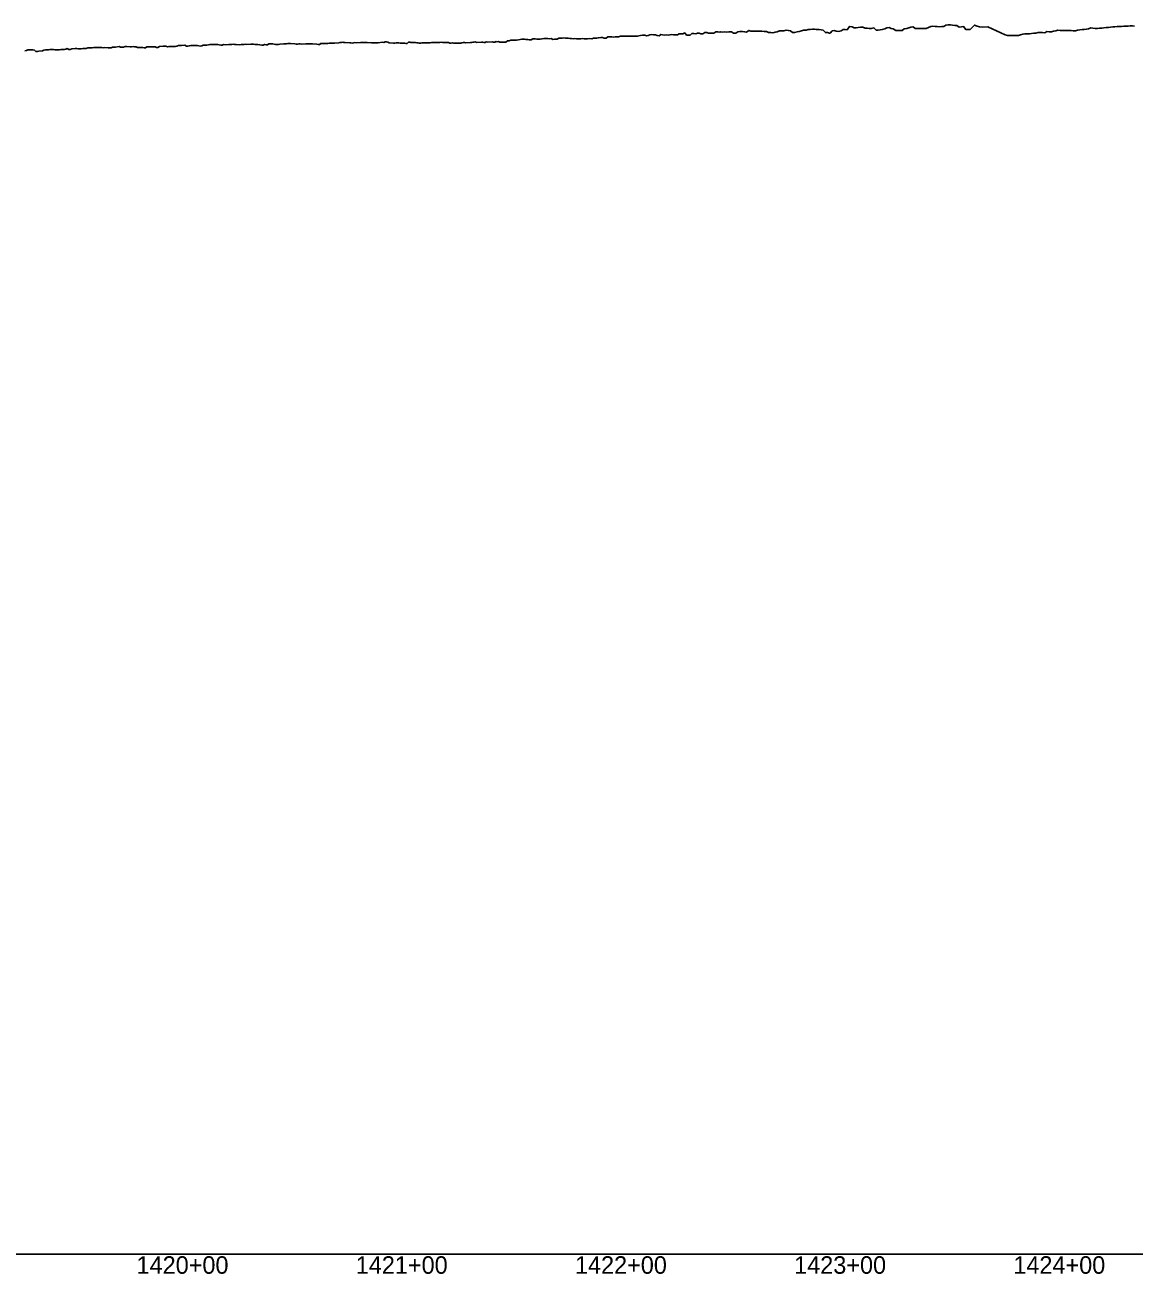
# Model space of a CAD drawing. Extents: x -3793 to 50787, y -1075 to 6138.
# Drawn here: x 29308 to 29813, y 991 to 1561 of the extents above; entities that cross this region are included whole.
import ezdxf

# ---------------------------------------------------------------- set-up
doc = ezdxf.new("R2010")
doc.units = 0
for name, color, linetype in [('RD_DDB_Profile_EX', 7, 'Continuous'), ('RD_DDB_StaTX', 7, 'Continuous'), ('RD_GPK_Profile_Cell', 7, 'Continuous')]:
    doc.layers.add(name, color=color, linetype=linetype)

msp = doc.modelspace()

# ---------------------------------------------------------------- linework, layer by layer
at = {"layer": 'RD_DDB_Profile_EX'}
for points in [[(29510.727296, 1552.70008), (29511.289844, 1552.672055), (29511.85211, 1552.89572), (29512.415515, 1552.95213), (29512.978802, 1553.00853), (29513.541972, 1552.811455), (29515.735563, 1552.906025), (29516.294395, 1552.90612), (29516.852944, 1552.736545), (29517.412638, 1552.73666), (29517.972213, 1553.044545), (29518.531671, 1552.820815), (29520.74402, 1553.006905), (29521.299048, 1552.896055), (29521.853791, 1552.83801), (29522.409686, 1553.143875), (29522.965461, 1553.1162), (29523.521117, 1553.1441), (29524.080917, 1552.9194), (29524.637441, 1552.863865), (29526.820946, 1552.860575), (29527.597675, 1553.52095), (29528.374319, 1553.521115), (29529.15088, 1553.793085), (29530.270517, 1553.864675), (29531.045117, 1553.861825), (29531.821316, 1553.86199), (29532.59743, 1553.97856), (29533.37346, 1554.05632), (29534.149406, 1554.211665), (29535.272139, 1554.27204), (29536.046109, 1554.036665), (29536.821687, 1554.11438), (29537.597179, 1553.959455), (29538.372587, 1553.959625), (29539.150156, 1554.422295), (29540.272077, 1554.4152), (29541.04711, 1554.29911), (29541.822059, 1554.260515), (29542.596922, 1554.22193), (29543.3717, 1554.3383), (29544.148651, 1554.49078), (29545.273723, 1554.494795), (29546.040367, 1554.572335), (29546.814688, 1554.456335), (29547.588923, 1554.49519), (29548.364538, 1554.10523), (29549.139398, 1554.22163), (29550.26763, 1554.305325), (29551.041392, 1554.653625), (29551.815068, 1554.769815), (29552.588659, 1554.769965), (29553.363636, 1554.8061), (29554.137855, 1554.69011), (29555.269317, 1554.69444), (29556.042427, 1554.578645), (29556.81545, 1554.50151), (29557.589064, 1554.45997), (29558.36272, 1554.498815), (29559.136289, 1554.344255), (29560.271021, 1554.45163), (29561.043471, 1554.37459), (29561.815834, 1554.52924), (29562.58879, 1554.448645), (29563.361788, 1554.448835), (29564.134699, 1554.449025), (29565.272744, 1554.48882), (29566.044525, 1554.45044), (29566.816219, 1554.68212), (29567.588509, 1554.678805), (29568.360841, 1554.678995), (29569.133086, 1554.872255), (29570.274485, 1554.957555), (29571.045589, 1554.996295), (29571.816474, 1554.68423), (29572.58822, 1554.68444), (29573.359879, 1555.26339), (29574.131449, 1555.263565), (29575.276244, 1555.303155), (29576.046662, 1555.22631), (29576.81686, 1555.261555), (29577.587925, 1555.30029), (29578.358901, 1555.33902), (29579.129788, 1555.57048), (29580.278023, 1555.621485), (29581.046786, 1555.57983), (29581.817248, 1555.58001), (29582.589017, 1555.573465), (29583.367111, 1555.56011), (29584.149479, 1555.627845), (29585.263496, 1555.632895), (29586.037114, 1555.584045), (29586.815605, 1555.570515), (29587.600158, 1555.835055), (29588.381972, 1555.9438), (29589.176798, 1556.01378), (29590.229218, 1556.14469), (29591.014, 1555.81378), (29591.80592, 1555.921455), (29592.603113, 1556.269125), (29593.407295, 1556.41578)], [(29593.407295, 1556.41578), (29594.21612, 1556.285525), (29595.199443, 1556.2209), (29595.998982, 1555.97004), (29596.803798, 1555.79464), (29597.615202, 1556.35215), (29598.432166, 1556.221055), (29599.249294, 1556.126605), (29600.159919, 1556.194445), (29600.973863, 1556.101645), (29601.793485, 1556.25508), (29602.618844, 1556.3683), (29603.4518, 1556.18855), (29604.289823, 1556.2192), (29605.128945, 1556.256815), (29605.95708, 1556.620805), (29606.790954, 1556.69085), (29607.632024, 1556.722835), (29608.47916, 1557.09289), (29609.326912, 1556.105155), (29610.085561, 1556.086265), (29610.929639, 1556.074315), (29611.779919, 1556.91623), (29612.637342, 1556.775465), (29613.501325, 1556.722855), (29614.371736, 1556.929225), (29615.050946, 1556.93858), (29615.909468, 1556.70917), (29616.776903, 1556.65544), (29617.650918, 1557.344705), (29618.531587, 1557.249085), (29619.413413, 1557.061545), (29620.003052, 1557.045935), (29620.880634, 1557.03741), (29621.765031, 1556.984395), (29622.657268, 1557.597735), (29623.556734, 1557.59126), (29624.463276, 1557.49472), (29624.964144, 1557.536325), (29625.857871, 1557.434625), (29626.761432, 1557.561945), (29627.672249, 1557.507985), (29628.592665, 1557.58805), (29629.510375, 1557.62567), (29629.910933, 1557.64706), (29630.82599, 1557.037655), (29631.74858, 1557.025875), (29632.67983, 1557.61592), (29633.619095, 1557.74685), (29634.566201, 1557.737865), (29634.866917, 1557.73588), (29635.800138, 1557.67666), (29636.744278, 1557.47764), (29637.696472, 1558.277565), (29638.659316, 1557.885145), (29639.817035, 1557.881045), (29640.764632, 1557.92032), (29641.729951, 1557.957005), (29642.705538, 1557.8994), (29643.689758, 1557.84129), (29644.753892, 1557.82962), (29645.735058, 1557.81984), (29646.725108, 1557.312235), (29647.724836, 1557.249965), (29648.716022, 1557.219115), (29649.741974, 1557.43547), (29650.728297, 1557.549385), (29651.718029, 1558.01174), (29652.699698, 1558.02468), (29653.78656, 1558.13589), (29654.774013, 1558.29865), (29655.751372, 1558.262075), (29656.722276, 1558.03236), (29657.685961, 1557.231135), (29658.643084, 1557.246435), (29659.81158, 1557.653895), (29660.762537, 1557.81153), (29661.717088, 1558.067605), (29662.664218, 1558.36462), (29663.887678, 1558.42827), (29664.840344, 1558.63242), (29665.783709, 1558.73752), (29666.72089, 1558.83831), (29667.656454, 1558.881245), (29668.592367, 1558.647095), (29669.531158, 1558.59618), (29669.845994, 1558.616765), (29670.783212, 1558.47594), (29671.720296, 1558.33055), (29672.65873, 1557.29807), (29673.599038, 1557.245125), (29674.538691, 1557.056915), (29674.840419, 1557.04589), (29675.779008, 1558.121865), (29676.719947, 1558.21571), (29677.661756, 1557.83415), (29678.603913, 1557.833885), (29679.83264, 1558.132795), (29680.774824, 1558.69421), (29681.719361, 1558.646745), (29682.664769, 1558.452915)], [(29682.664769, 1558.452915), (29683.610527, 1560.06029), (29684.824896, 1559.82218), (29685.771904, 1559.44317), (29686.718779, 1559.43931), (29687.667006, 1559.62875), (29688.617114, 1559.672555), (29689.819433, 1559.786535), (29690.767759, 1559.307305), (29691.718441, 1559.35461), (29692.669996, 1559.112275), (29693.623674, 1559.1076), (29694.81176, 1559.437465), (29695.763633, 1558.383615), (29696.717867, 1558.38334), (29697.672974, 1558.473455), (29698.628431, 1558.61649), (29699.80412, 1558.962325), (29700.760774, 1559.488255), (29701.717295, 1559.62731), (29702.675173, 1559.05238), (29703.634935, 1558.951385), (29704.798767, 1558.17858), (29705.756688, 1558.220655), (29706.716728, 1558.21476), (29707.678127, 1558.21446), (29708.641414, 1559.02661), (29709.791197, 1559.09404), (29710.752619, 1559.474015), (29711.716406, 1559.762895), (29712.68107, 1559.95108), (29713.646084, 1559.17891), (29714.78366, 1559.075895), (29715.74982, 1559.123925), (29716.715846, 1559.11845), (29717.683232, 1559.0698), (29718.652508, 1559.06426), (29719.778415, 1559.547395), (29720.745789, 1560.02725), (29721.715289, 1560.119855), (29722.686152, 1560.02255), (29723.658906, 1559.96947), (29724.770946, 1559.96161), (29725.741777, 1560.00601), (29726.714979, 1560.10312), (29727.68906, 1560.68358), (29728.663493, 1560.73212), (29729.763509, 1560.727045), (29730.739036, 1560.629315), (29731.71443, 1560.528185), (29732.691187, 1560.479165), (29733.669838, 1559.742195), (29734.756104, 1559.880965), (29735.735061, 1559.978655), (29736.713884, 1558.70053), (29737.694072, 1558.700255), (29738.676157, 1558.694855), (29739.750998, 1559.767985), (29740.731103, 1560.69741), (29741.868801, 1560.23845), (29742.909528, 1559.877205), (29744.134382, 1559.70281), (29746.828724, 1559.838205), (29754.75057, 1556.200525), (29755.73255, 1555.98161), (29756.732007, 1555.97369), (29757.731753, 1555.970895), (29758.731212, 1555.91378), (29759.73096, 1555.859315), (29760.730541, 1556.000515), (29761.732021, 1556.30719), (29762.734854, 1556.519765), (29763.737686, 1556.679225), (29764.73918, 1556.733675), (29765.742016, 1556.747955), (29766.743519, 1556.85928), (29767.746336, 1557.01942), (29768.747845, 1557.026915), (29769.750686, 1557.232655), (29770.752204, 1557.28878), (29771.75505, 1557.30325), (29772.756577, 1557.16106), (29773.759427, 1557.748595), (29774.760916, 1557.59669), (29775.763766, 1557.55201), (29776.765309, 1557.89285), (29777.768163, 1558.0454), (29778.769715, 1558.33574), (29779.769966, 1558.24091), (29780.770157, 1558.18916), (29781.77041, 1558.142125), (29782.770664, 1558.149655), (29783.769596, 1558.197545), (29784.769849, 1558.1961), (29785.760533, 1558.105705), (29786.760728, 1558.065195), (29787.760986, 1558.30035), (29788.761118, 1558.5394), (29789.761186, 1558.643945), (29790.761254, 1558.73724), (29791.760033, 1558.83059)], [(29791.760033, 1558.83059), (29792.760102, 1558.926285), (29793.760172, 1559.450195), (29794.760304, 1559.259125), (29795.760374, 1559.128815), (29796.760443, 1559.17668), (29797.760513, 1559.235465), (29798.760205, 1559.333545), (29799.758946, 1559.37677), (29800.759018, 1559.52894), (29801.759089, 1559.587455), (29802.759219, 1559.733495), (29803.75929, 1559.833555), (29804.759362, 1559.93573), (29805.759433, 1560.029425), (29806.759562, 1560.03394), (29807.758314, 1560.077115), (29808.758387, 1560.173075), (29809.75846, 1560.175185), (29810.758589, 1560.193955), (29811.758662, 1560.36522), (29812.758735, 1560.269395), (29813.758807, 1560.22975)], [(29307.506444, 1548.961935), (29308.182165, 1549.09719), (29308.860372, 1549.399815), (29310.482474, 1549.38743), (29311.155816, 1549.318495), (29311.831006, 1549.18356), (29312.506881, 1548.607315), (29313.184486, 1548.638735), (29313.863825, 1548.83966), (29315.480419, 1548.99141), (29316.155888, 1549.29545), (29316.831129, 1549.360935), (29317.508117, 1549.46044), (29318.185134, 1549.39285), (29318.864701, 1549.52641), (29320.4803, 1549.482655), (29321.154893, 1549.413295), (29321.83138, 1549.447215), (29322.50857, 1549.411585), (29323.187533, 1549.37586), (29323.865589, 1549.47768), (29325.480173, 1549.56335), (29326.154943, 1549.662885), (29326.831629, 1549.933625), (29327.509027, 1549.55953), (29328.186455, 1549.559645), (29328.863782, 1549.89845), (29330.482072, 1549.967515), (29331.156075, 1549.9996), (29331.832012, 1549.830735), (29332.508666, 1549.82884), (29333.185351, 1549.896615), (29333.861934, 1549.964385), (29335.484003, 1550.066715), (29336.157225, 1550.368525), (29336.832397, 1550.36862), (29337.508293, 1550.333225), (29338.184219, 1550.367115), (29338.860043, 1550.401), (29340.485967, 1550.48681), (29341.158392, 1550.485025), (29341.832784, 1550.417695), (29342.507906, 1550.449575), (29343.183059, 1550.38216)], [(29343.183059, 1550.38216), (29343.858108, 1550.38227), (29345.487966, 1550.354745), (29346.159577, 1550.31922), (29346.833173, 1550.285655), (29347.507505, 1550.5872), (29348.18187, 1550.553565), (29348.856129, 1550.654805), (29350.49, 1550.986895), (29351.16078, 1550.681785), (29351.833564, 1550.614675), (29352.506242, 1550.61484), (29353.18065, 1550.915045), (29353.854103, 1550.88151), (29355.49207, 1550.74032), (29356.162003, 1550.7718), (29356.833958, 1550.8391), (29357.505805, 1550.738445), (29358.1794, 1550.702685), (29358.852029, 1550.400095), (29360.494178, 1550.40719), (29361.163246, 1550.471685), (29361.834354, 1550.337625), (29362.505354, 1550.237135), (29363.178117, 1550.8054), (29363.849906, 1550.805515), (29365.496324, 1550.794595), (29366.164509, 1550.792585), (29366.834753, 1550.792695), (29367.504887, 1550.524775), (29368.176801, 1550.522375), (29368.847732, 1550.92511), (29370.498511, 1551.029635), (29371.165794, 1550.99404), (29371.835154, 1551.128015), (29372.504404, 1550.826985), (29373.175451, 1550.92509), (29373.845506, 1550.858205), (29375.500739, 1550.898035), (29376.168276, 1550.898175), (29376.835558, 1551.096195), (29377.503905, 1551.330225), (29378.174066, 1551.42876), (29378.843225, 1551.395395), (29380.503009, 1551.483665), (29381.169616, 1551.050585), (29381.835965, 1551.081295), (29382.496724, 1551.248265), (29383.16598, 1551.31273), (29383.834236, 1551.31286), (29385.498644, 1551.40281), (29386.164311, 1551.3364), (29386.829707, 1551.200465), (29387.495306, 1551.10381), (29388.160635, 1551.270315), (29388.82585, 1551.56985), (29390.505559, 1551.593175), (29391.169348, 1551.694985), (29391.830763, 1551.79431), (29392.492066, 1551.76136), (29393.153255, 1551.8276), (29393.811345, 1551.7638), (29395.517111, 1551.76981), (29396.174447, 1551.60563), (29396.83167, 1551.54005), (29397.487889, 1551.57556), (29398.143838, 1551.772485), (29398.799675, 1551.739805), (29400.526518, 1551.88488), (29401.180813, 1551.887695), (29401.832742, 1551.88784), (29402.484557, 1551.95316), (29403.134328, 1551.858255), (29403.784875, 1551.890935), (29405.538297, 1551.739955), (29406.186037, 1551.837215), (29406.833664, 1551.8697), (29407.480291, 1551.87179), (29408.12665, 1551.936535), (29408.772896, 1551.775055), (29410.547942, 1551.923955), (29411.192526, 1551.958765), (29411.834752, 1551.9589), (29412.476866, 1551.86272), (29413.116943, 1551.76937), (29413.757792, 1551.769525), (29415.559955, 1551.578675), (29416.197879, 1551.578795), (29416.835692, 1551.86589), (29417.472508, 1551.7086), (29418.109056, 1551.708705), (29418.745493, 1552.09072), (29420.569846, 1552.204965), (29421.204495, 1551.953875), (29421.836796, 1551.827545), (29422.468985, 1551.85928), (29423.099145, 1551.893235), (29423.730075, 1551.988005), (29425.582101, 1552.180545), (29426.209983, 1552.11791), (29426.837909, 1552.15208)], [(29426.837909, 1552.15208), (29427.464531, 1552.340195), (29428.091043, 1552.27767), (29428.717444, 1552.246475), (29430.592248, 1552.065935), (29431.21673, 1552.0369), (29431.838875, 1552.03701), (29432.460908, 1552.130415), (29433.080922, 1552.070285), (29433.701702, 1552.039345), (29435.604753, 1552.19886), (29436.222357, 1552.137245), (29436.840004, 1552.07827), (29437.456356, 1552.10923), (29438.072596, 1552.17099), (29438.688726, 1552.140315), (29440.615165, 1552.051855), (29441.22924, 1551.90132), (29441.840989, 1551.809705), (29442.452627, 1552.299125), (29443.062257, 1552.27055), (29443.672648, 1552.209605), (29445.627928, 1552.29498), (29446.235011, 1552.416485), (29446.842137, 1552.418595), (29447.447973, 1552.47928), (29448.0537, 1552.38852), (29448.659316, 1552.38863), (29450.638616, 1552.59464), (29451.239675, 1552.74299), (29451.842833, 1552.74311), (29452.44588, 1552.83369), (29453.048817, 1552.77351), (29453.651644, 1552.71334), (29455.645024, 1552.561345), (29456.244414, 1552.56145), (29456.843537, 1552.49957), (29457.443738, 1552.559695), (29458.043828, 1552.679825), (29458.643807, 1552.649915), (29460.65156, 1552.676515), (29461.248039, 1552.676615), (29461.844251, 1552.734575), (29462.441546, 1552.73467), (29463.038729, 1552.764625), (29463.6358, 1552.675145), (29465.658229, 1552.559885), (29466.251735, 1552.5303), (29466.84513, 1552.58972), (29467.439301, 1552.618), (29468.033516, 1552.61808), (29468.627618, 1552.52903), (29470.665033, 1552.84214), (29471.255505, 1552.812755), (29471.845863, 1553.04899), (29472.437002, 1553.01749), (29473.028185, 1552.928925), (29473.619256, 1552.66303), (29475.671978, 1552.487365), (29476.259349, 1552.487485), (29476.846606, 1552.546325), (29477.43375, 1552.60515), (29478.022734, 1552.514985), (29478.610707, 1552.4563), (29480.679069, 1552.444175), (29481.263271, 1552.32749), (29481.847359, 1552.298425), (29482.431333, 1552.882495), (29483.017158, 1552.822595), (29483.601965, 1552.705705), (29485.686309, 1552.670615), (29486.267273, 1552.641665), (29486.848123, 1552.583685), (29487.428857, 1552.409575), (29488.009478, 1552.409695), (29488.593025, 1552.523955), (29490.693705, 1552.573765), (29491.271358, 1552.51613), (29491.848897, 1552.54512), (29492.42632, 1552.63184), (29493.003628, 1552.68968), (29493.583879, 1552.774655), (29495.701261, 1552.78133), (29496.27553, 1552.810125), (29496.849682, 1552.810215), (29497.423719, 1552.839005), (29497.99764, 1552.810395), (29498.571446, 1552.724405), (29500.711308, 1552.6886), (29501.279789, 1552.373105), (29501.850479, 1552.37323), (29502.421053, 1552.65862), (29502.99151, 1552.487575), (29503.561851, 1552.487685), (29505.719213, 1552.452755), (29506.284141, 1552.479205), (29506.851288, 1552.621075), (29507.418319, 1552.677865), (29507.985233, 1552.706295), (29508.552029, 1552.64969), (29510.727296, 1552.70008)]]:
    msp.add_lwpolyline(points, dxfattribs=at)
at = {"layer": 'RD_GPK_Profile_Cell'}
msp.add_line((1000, 1000), (46600, 1000), dxfattribs=at)

# ---------------------------------------------------------------- texts
at = {"layer": 'RD_DDB_StaTX'}
for s, p in [('1420+00', (29358.415471, 991)), ('1421+00', (29458.415471, 991)), ('1422+00', (29558.415471, 991)), ('1423+00', (29658.415471, 991)), ('1424+00', (29758.415471, 991))]:
    msp.add_text(s, height=8, dxfattribs=at).set_placement(p)

doc.saveas('drawing.dxf')
